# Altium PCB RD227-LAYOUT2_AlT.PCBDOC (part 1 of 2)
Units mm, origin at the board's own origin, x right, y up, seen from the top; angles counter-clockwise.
Board outline 90 x 40 mm, 4 copper layers (TOP, Mid-Layer 1, Mid-Layer 2, BOTTOM), stack 0.711 mm thick; 157 components, 70 nets, 396 pads, 438 vias.
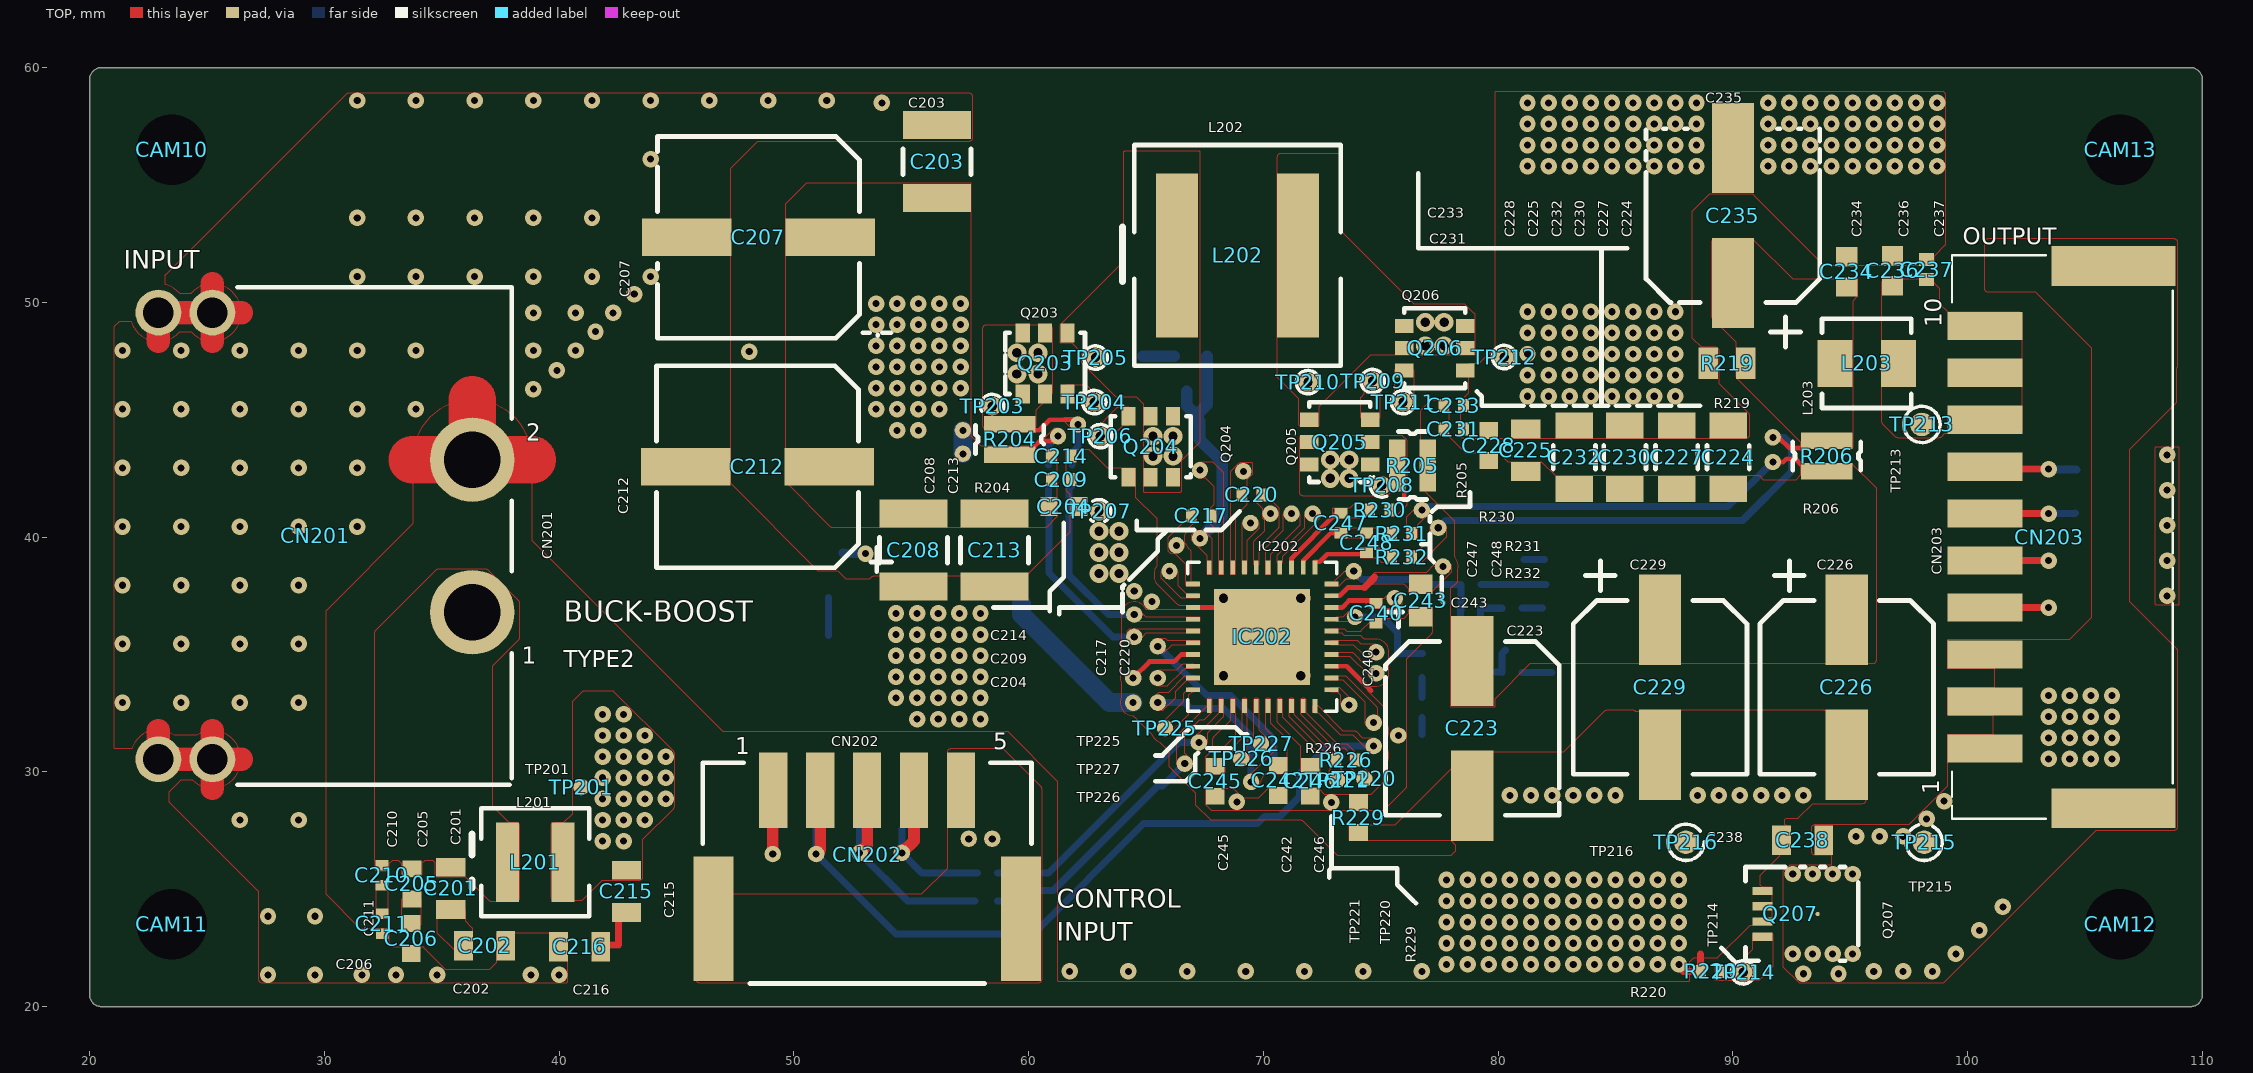
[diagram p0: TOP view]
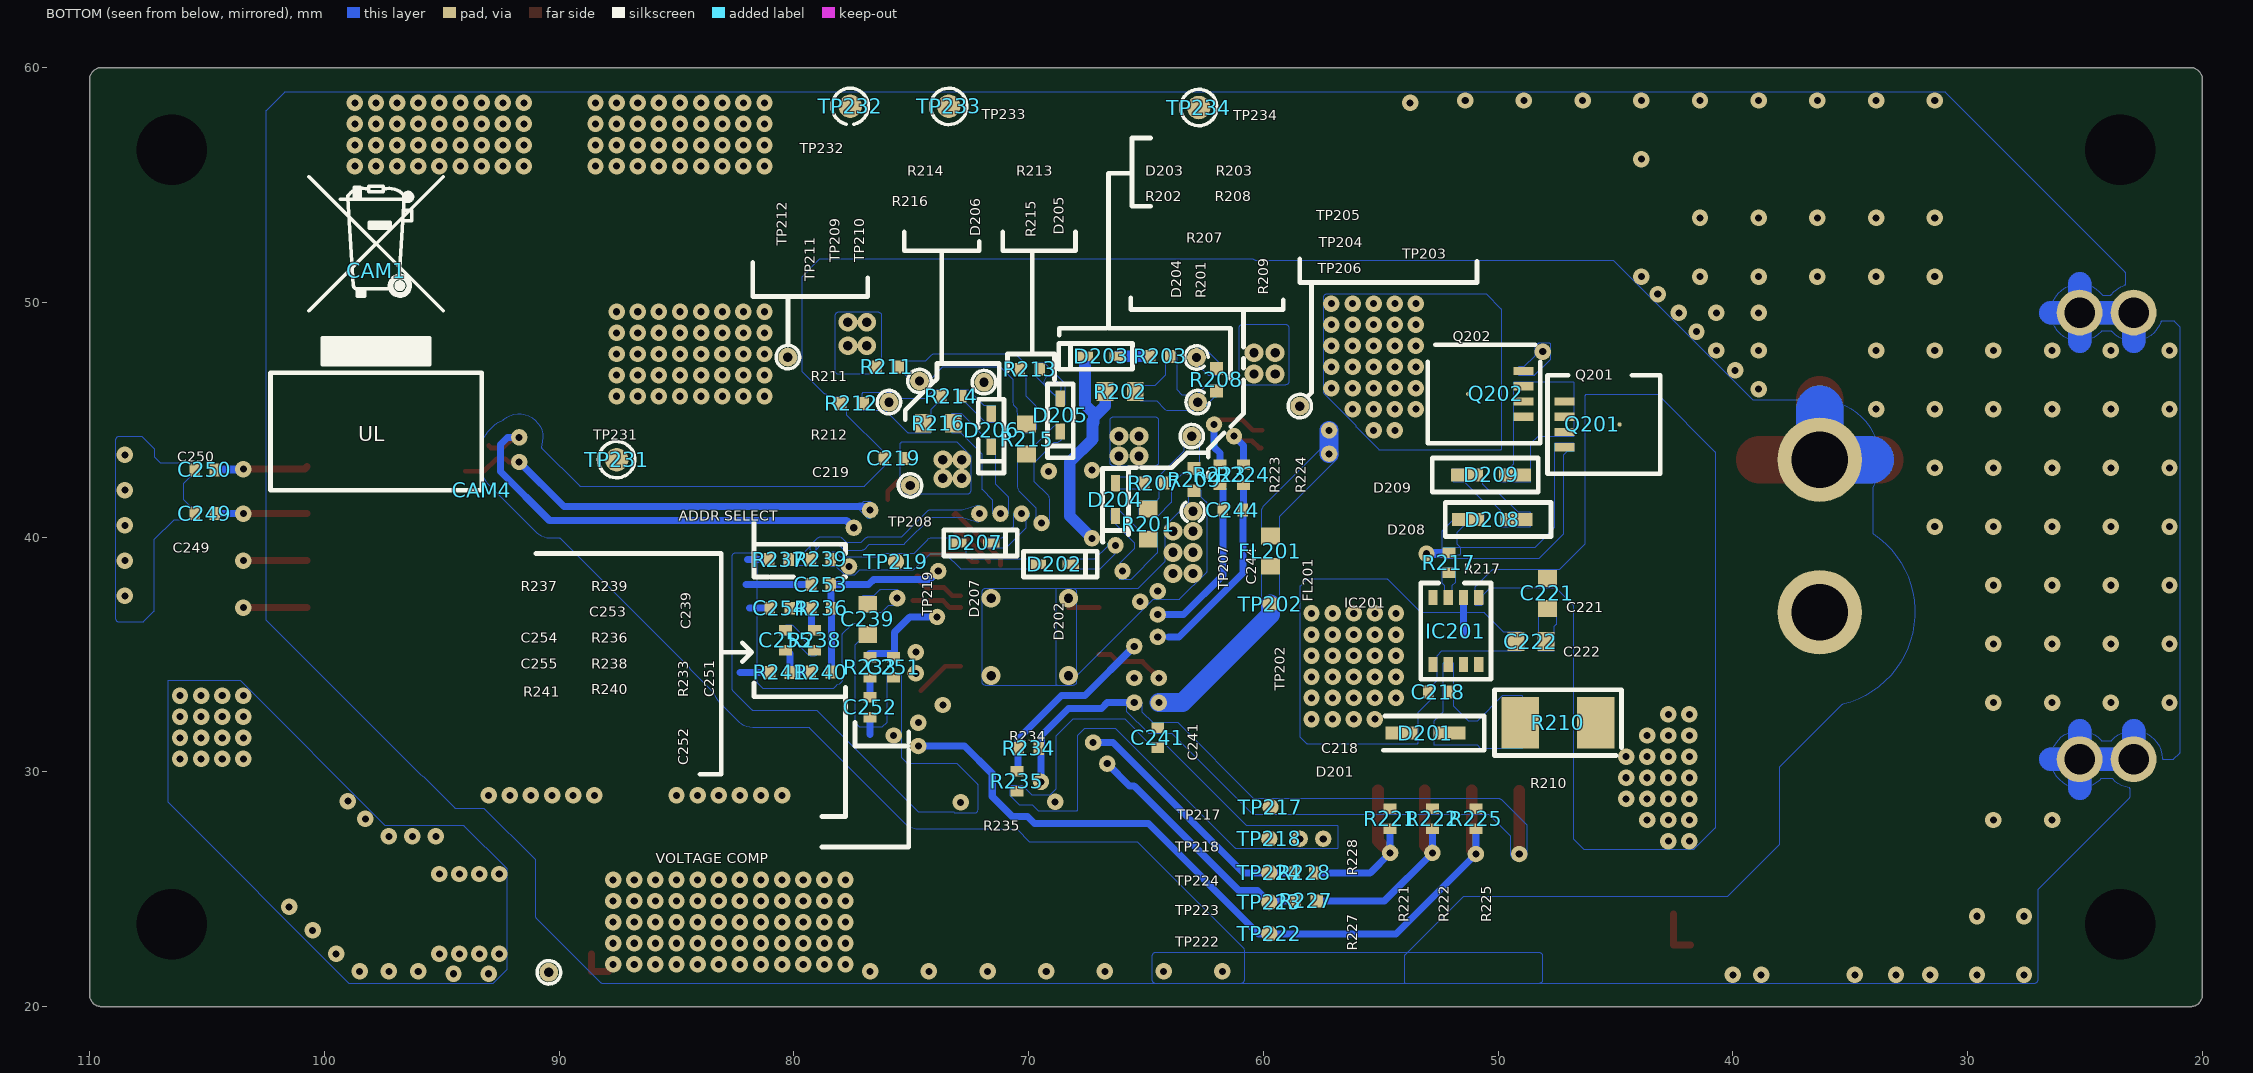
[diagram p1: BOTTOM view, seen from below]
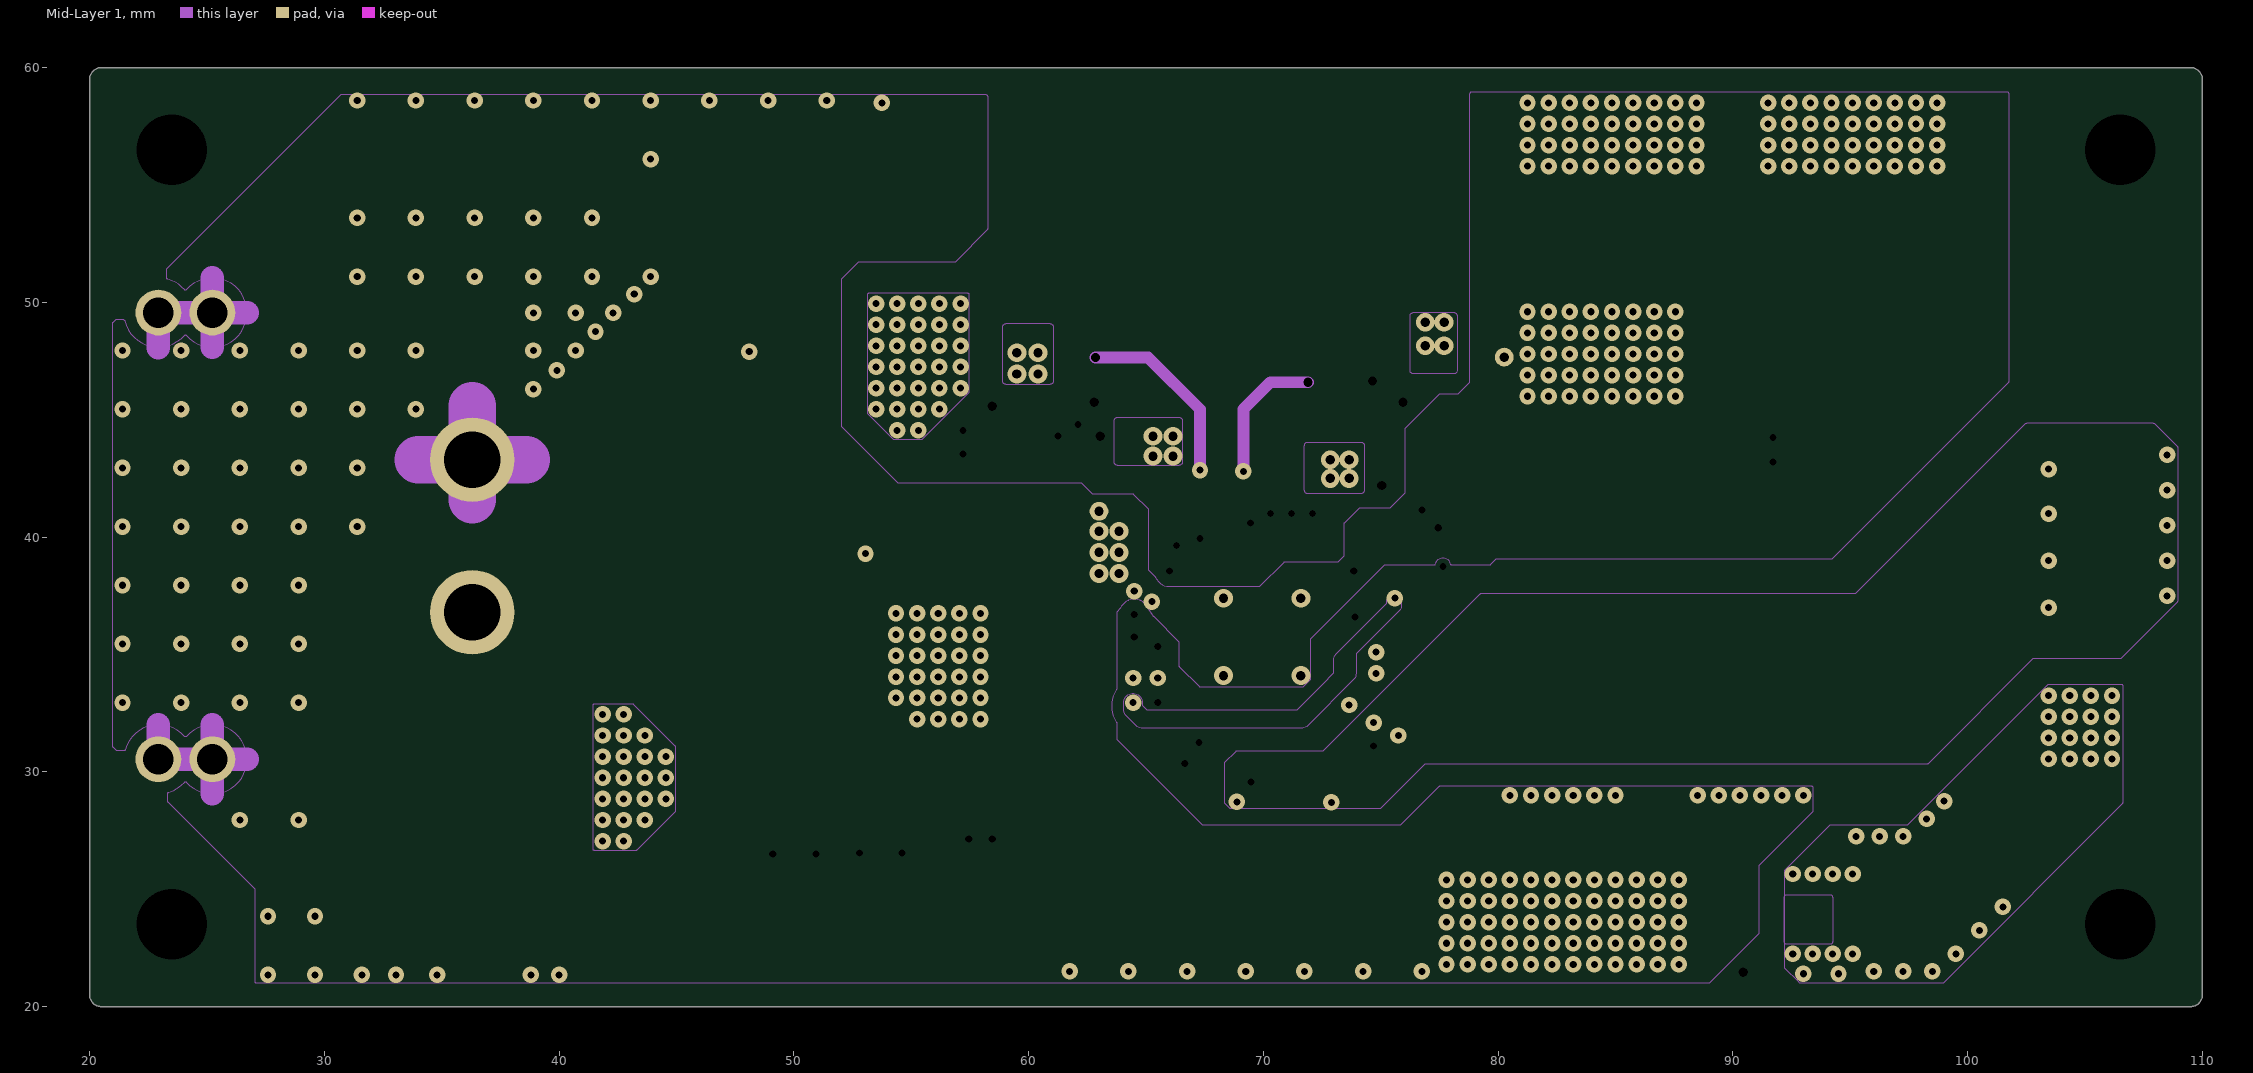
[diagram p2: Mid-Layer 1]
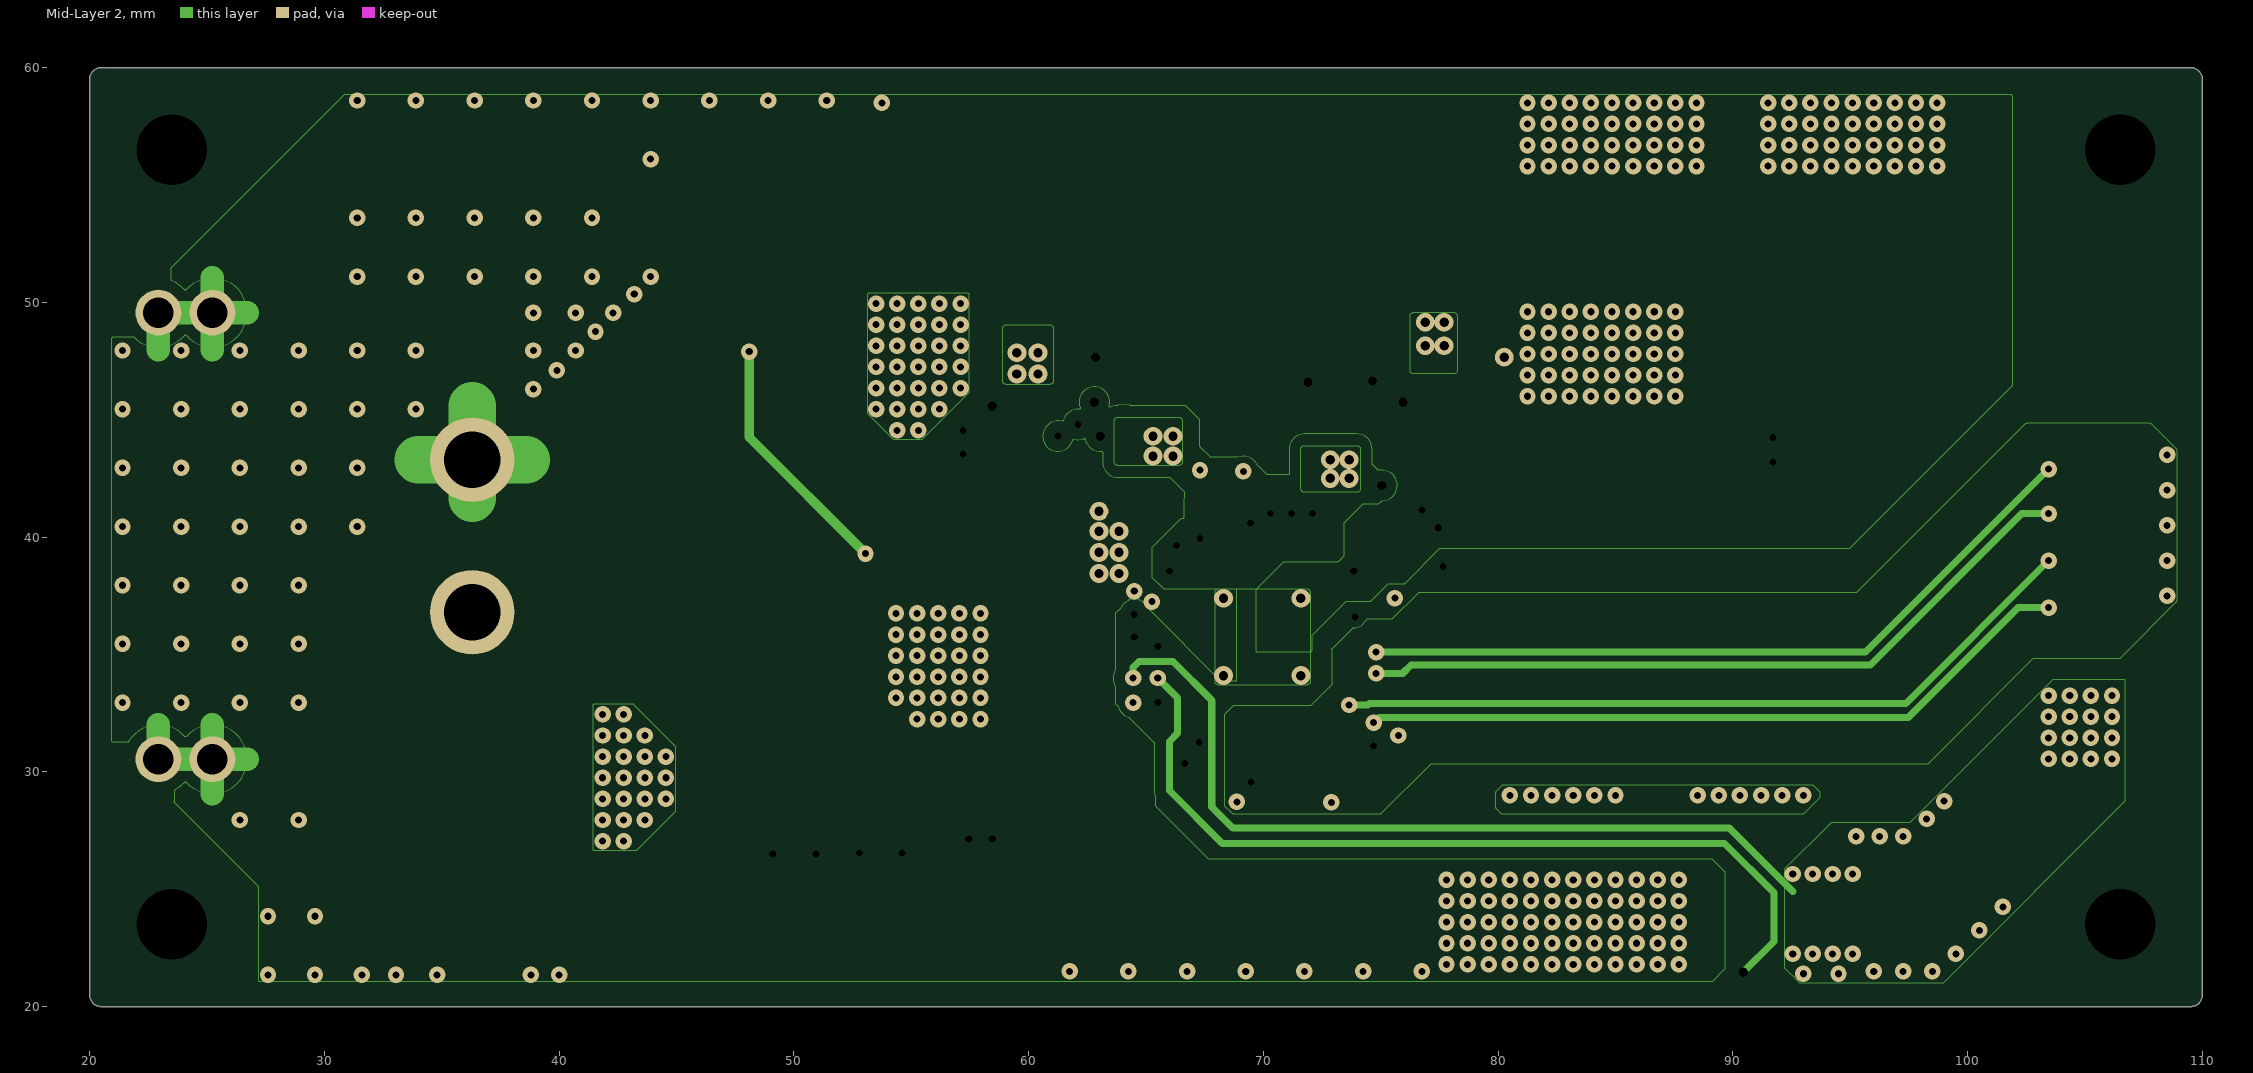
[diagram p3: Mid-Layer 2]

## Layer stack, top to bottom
Top Solder: solder mask 0.0102, Solder Resist, Dk 3.5
TOP: signal copper (thickness not stored)
Mid-Layer 1: signal copper 0.0356
Dielectric2: dielectric 0.32, FR-4, Dk 4.8
Mid-Layer 2: signal copper 0.0356
Dielectric3: dielectric 0.32, FR-4, Dk 4.8
BOTTOM: signal copper (thickness not stored)
Bottom Solder: solder mask 0.0102, Solder Resist, Dk 3.5

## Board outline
20,59.5 cw(c20.5,59.5) 20.5,60 109.5,60 cw(c109.5,59.5) 110,59.5 110,20.5 cw(c109.5,20.5) 109.5,20 20.5,20 cw(c20.5,20.5) 20,20.5

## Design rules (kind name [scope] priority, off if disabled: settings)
AssemblyTestPointUsage [All] p0: scope1count=1 scope1_0_kind=Board scope1_0_value=Board scope2count=1 scope2_0_kind=Board scope2_0_value=Board commentlength=0
AssemblyTestpoint [All] p0: scope1count=1 scope1_0_kind=Board scope1_0_value=Board scope2count=1 scope2_0_kind=Board scope2_0_value=Board commentlength=0
Clearance [All] p0: scope1count=1 scope1_0_kind=Board scope1_0_value=Board scope2count=1 scope2_0_kind=Board scope2_0_value=Board commentlength=0 gap=0.1
Clearance [All] p1: gap=0.1 ignorepadtopadclearanceinfootprint=TRUE except(0.11: SMDPad-Via; 0.15: SMDPad-SMDPad THPad-THPad Via-Via Via-Fill Via-Poly Via-Region; 0.25: SMDPad-Fill SMDPad-Poly SMDPad-Region THPad-Fill THPad-Poly THPad-Region Fill-Fill Fill-Poly Fill-Region Poly-Poly Poly-Region Region-Region; 1: Arc-Hole Track-Hole SMDPad-Hole THPad-Hole Fill-Hole Poly-Hole Region-Hole Text-Hole; 1.75: THPad-Via Via-Hole; 3: SMDPad-THPad)
ComponentClearance [All] p0: scope1count=1 scope1_0_kind=Board scope1_0_value=Board scope2count=1 scope2_0_kind=Board scope2_0_value=Board commentlength=0 gap=0.254 collisioncheckmode=3
DiffPairsRouting [All] p0: scope1count=1 scope1_0_kind=Board scope1_0_value=Board scope2count=1 scope2_0_kind=Board scope2_0_value=Board commentlength=0
FabricationTestPointUsage [All] p0: scope1count=1 scope1_0_kind=Board scope1_0_value=Board scope2count=1 scope2_0_kind=Board scope2_0_value=Board commentlength=0 valid=0 allowmultiple=FALSE
FabricationTestpoint [All] p0: scope1count=1 scope1_0_kind=Board scope1_0_value=Board scope2count=1 scope2_0_kind=Board scope2_0_value=Board commentlength=0 side=3 testpointundercomponent=TRUE minsize=1.016 maxsize=2.54 preferedsize=1.524 minholesize=0 maxholesize=1.016 preferedholesize=0.813 testpointgrid=0.025
FanoutControl Fanout_Default [All] p0: scope1count=1 scope1_0_kind=Board scope1_0_value=Board scope2count=1 scope2_0_kind=Board scope2_0_value=Board commentlength=30 // Fanout_Default (Default Rule)
FanoutControl Fanout_Small [All] p0 off: scope1count=1 scope1_0_kind=Board scope1_0_value=Board scope2count=1 scope2_0_kind=Board scope2_0_value=Board commentlength=84 // Protel DXP Scope 1 Expression Was: (CompPinCount < 5)   Fanout_Small (Default Rule)
FanoutControl Fanout_SOIC [All] p0 off: scope1count=1 scope1_0_kind=Board scope1_0_value=Board scope2count=1 scope2_0_kind=Board scope2_0_value=Board commentlength=71 // Protel DXP Scope 1 Expression Was: IsSOIC   Fanout_SOIC (Default Rule)
FanoutControl Fanout_LCC [All] p0 off: scope1count=1 scope1_0_kind=Board scope1_0_value=Board scope2count=1 scope2_0_kind=Board scope2_0_value=Board commentlength=69 // Protel DXP Scope 1 Expression Was: IsLCC   Fanout_LCC (Default Rule)
FanoutControl Fanout_BGA [All] p0 off: scope1count=1 scope1_0_kind=Board scope1_0_value=Board scope2count=1 scope2_0_kind=Board scope2_0_value=Board commentlength=69 // Protel DXP Scope 1 Expression Was: IsBGA   Fanout_BGA (Default Rule)
Height [All] p0: scope1count=1 scope1_0_kind=Board scope1_0_value=Board scope2count=1 scope2_0_kind=Board scope2_0_value=Board commentlength=0
HoleSize [All] p0: scope1count=1 scope1_0_kind=Board scope1_0_value=Board scope2count=1 scope2_0_kind=Board scope2_0_value=Board commentlength=0 absolutevalues=TRUE maxlimit=100 minlimit=0.001 maxpercent=80.000 minpercent=20.000
HoleSize [All] p1: absolutevalues=TRUE maxlimit=100 minlimit=0.001 maxpercent=80.000 minpercent=20.000
HoleToHoleClearance [All] p0: scope1count=1 scope1_0_kind=Board scope1_0_value=Board scope2count=1 scope2_0_kind=Board scope2_0_value=Board commentlength=0
HoleToHoleClearance [All] p1: gap=0.45 allowstackedmicrovias=FALSE
LayerPairs [All] p0: scope1count=1 scope1_0_kind=Board scope1_0_value=Board scope2count=1 scope2_0_kind=Board scope2_0_value=Board commentlength=0 enforce=TRUE
MinimumSolderMaskSliver [All] p0: scope1count=1 scope1_0_kind=Board scope1_0_value=Board scope2count=1 scope2_0_kind=Board scope2_0_value=Board commentlength=0
MinimumSolderMaskSliver [All] p1: minsoldermaskwidth=0.1
NetAntennae [All] p0: scope1count=1 scope1_0_kind=Board scope1_0_value=Board scope2count=1 scope2_0_kind=Board scope2_0_value=Board commentlength=0
NetAntennae [All] p1: netantennaetolerance=100
PasteMaskExpansion [All] p0: scope1count=1 scope1_0_kind=Board scope1_0_value=Board scope2count=1 scope2_0_kind=Board scope2_0_value=Board commentlength=0 expansion=0
PlaneClearance [All] p0: scope1count=1 scope1_0_kind=Board scope1_0_value=Board scope2count=1 scope2_0_kind=Board scope2_0_value=Board commentlength=0 clearance=0.001
PlaneClearance [All] p1: clearance=0.001
PlaneConnect [All] p0: scope1count=1 scope1_0_kind=Board scope1_0_value=Board scope2count=1 scope2_0_kind=Board scope2_0_value=Board commentlength=0 planeconnectstyle=Direct reliefexpansion=0.508 reliefentries=4 reliefconductorwidth=0.254 reliefairgap=0.254
PlaneConnect [All] p1: planeconnectstyle=Direct reliefexpansion=0.508 reliefentries=4 reliefconductorwidth=0.254 reliefairgap=0.254
PolygonConnect [All] p0: scope1count=1 scope1_0_kind=Board scope1_0_value=Board scope2count=1 scope2_0_kind=Board scope2_0_value=Board commentlength=0 connectstyle=Direct reliefconductorwidth=0.254 reliefentries=4 polygonreliefangle="90 Angle"
PolygonConnect [All] p1: connectstyle=Direct reliefconductorwidth=0.254 reliefentries=4 polygonreliefangle="90 Angle" airgapwidth=0.254
RoutingCorners [All] p0: scope1count=1 scope1_0_kind=Board scope1_0_value=Board scope2count=1 scope2_0_kind=Board scope2_0_value=Board commentlength=0 cornerstyle=45-Degree minsetback=2.54 maxsetback=2.54
RoutingLayers [All] p0: scope1count=1 scope1_0_kind=Board scope1_0_value=Board scope2count=1 scope2_0_kind=Board scope2_0_value=Board commentlength=0 top layer=Automatic mid layer 1=Automatic mid layer 2=Automatic bottom layer=Automatic
RoutingPriority [All] p0: scope1count=1 scope1_0_kind=Board scope1_0_value=Board scope2count=1 scope2_0_kind=Board scope2_0_value=Board commentlength=0
RoutingTopology [All] p0: scope1count=1 scope1_0_kind=Board scope1_0_value=Board scope2count=1 scope2_0_kind=Board scope2_0_value=Board commentlength=0 topology=Shortest
RoutingVias [All] p0: scope1count=1 scope1_0_kind=Board scope1_0_value=Board scope2count=1 scope2_0_kind=Board scope2_0_value=Board commentlength=0 holewidth=0.1 width=0.1 viastyle="Through Hole" minholewidth=0.001 minwidth=0.001 maxholewidth=100 maxwidth=100
RoutingVias [All] p1: holewidth=0.1 width=0.1 viastyle="Through Hole" minholewidth=0.001 minwidth=0.001 maxholewidth=100 maxwidth=100
ShortCircuit [All] p0: scope1count=1 scope1_0_kind=Board scope1_0_value=Board scope2count=1 scope2_0_kind=Board scope2_0_value=Board commentlength=0 allowed=FALSE
SilkToBoardRegionClearance [All] p0: scope1count=1 scope1_0_kind=Board scope1_0_value=Board scope2count=1 scope2_0_kind=Board scope2_0_value=Board commentlength=0
SilkToSilkClearance [All] p0: scope1count=1 scope1_0_kind=Board scope1_0_value=Board scope2count=1 scope2_0_kind=Board scope2_0_value=Board commentlength=0
SilkToSilkClearance [All] p1: silktosilkclearance=0.001
SilkToSolderMaskClearance [All] p0 off: scope1count=1 scope1_0_kind=Board scope1_0_value=Board scope2count=1 scope2_0_kind=Board scope2_0_value=Board commentlength=44 // Protel DXP Scope 1 Expression Was: IsPad
SilkToSolderMaskClearance [IsPad] p1: minsilkscreentomaskgap=0.11 clearancetoexposedcopper=TRUE
SolderMaskExpansion [All] p0: scope1count=1 scope1_0_kind=Board scope1_0_value=Board scope2count=1 scope2_0_kind=Board scope2_0_value=Board commentlength=0 expansion=0.001
SolderMaskExpansion [All] p1: expansion=0.001
UnRoutedNet [All] p0: scope1count=1 scope1_0_kind=Board scope1_0_value=Board scope2count=1 scope2_0_kind=Board scope2_0_value=Board commentlength=0
UnpouredPolygon [All] p0: scope1count=1 scope1_0_kind=Board scope1_0_value=Board scope2count=1 scope2_0_kind=Board scope2_0_value=Board commentlength=0
Width [All] p0: scope1count=1 scope1_0_kind=Board scope1_0_value=Board scope2count=1 scope2_0_kind=Board scope2_0_value=Board commentlength=0 maxlimit=1000 minlimit=2539.975 preferedwidth=0
Width [All] p1: maxlimit=1000 minlimit=2539.975 preferedwidth=0 toplayer_minwidth=0 midlayer1_minwidth=0 midlayer2_minwidth=0 bottomlayer_minwidth=0 minimp=50.000000 maximp=50.000000 favimp=50.000000
22 further rules are at their usual default settings.

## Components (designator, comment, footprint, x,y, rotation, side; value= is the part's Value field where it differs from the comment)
C201 "KC00060AKP" KC00060AKP 35.389,25.035 r90 top
C202 "KC00060AKP" KC00060AKP 36.828,22.597 r180 top
C203 "KCK03340AKP" KCK03340AKP 56.1,56 r270 top
C204 "KC00080AKP" KC00080AKP 61.5,41.3 r180 top
C205 "KC01340AKP" KC01340AKP 33.729,25.232 r90 top
C206 "KC01340AKP" KC01340AKP 33.7,22.9 r90 top
C207 "DC837K" DC837K 48.492,52.769 r0 top
C208 "KCK03340AKP" KCK03340AKP 55.1,39.45 r90 top
C209 "DC834K" DC834K 61.4,42.45 r180 top
C210 "DC834K" DC834K 32.45,25.6 r90 top
C211 "DC834K" DC834K 32.466,23.529 r90 top
C212 "DC837K" DC837K 48.45,43 r0 top
C213 "KCK03340AKP" KCK03340AKP 58.55,39.45 r90 top
C214 "DC834K" DC834K 61.4,43.45 r180 top
C215 "KC00060AKP" KC00060AKP 42.869,24.911 r90 top
C216 "KC00060AKP" KC00060AKP 40.874,22.545 r0 top
C217 "DC834K" DC834K 67.35,40.9 r0 top
C218 "DC934K" DC934K 52.55,33.4 r180 bottom
C219 "KC01540BKP01" KC01540BKP01 75.75,43.35 r0 bottom
C220 "DC834K" DC834K 69.5,41.8 r180 top
C221 "KC00080BKP" KC00080BKP 47.9,37.6 r90 bottom
C222 "KC00080BKP" KC00080BKP 48.6,35.55 r180 bottom
C223 "DC843R" DC843R 78.9,31.85 r90 top
C224 "KC00140AKP" KC00140AKP 89.8,43.4 r270 top
C225 "KC00060AKP" KC00060AKP 81.175,43.7 r270 top
C226 "DC843R" DC843R 94.85,33.6 r90 top
C227 "KC00140AKP" KC00140AKP 87.6,43.4 r270 top
C228 "KC00080AKP" KC00080AKP 79.6,43.9 r270 top
C229 "DC843R" DC843R 86.9,33.6 r90 top
C230 "KC00140AKP" KC00140AKP 85.4,43.4 r270 top
C231 "DC834K" DC834K 78.1,44.6 r180 top
C232 "KC00140AKP" KC00140AKP 83.25,43.4 r270 top
C233 "DC834K" DC834K 78.1,45.6 r180 top
C234 "KCK02380AKP01" KCK02380AKP01 94.85,51.3 r270 top
C235 "DC843R" DC843R 90,53.7 r270 top
C236 "KCK02380AKP01" KCK02380AKP01 96.8,51.35 r270 top
C237 "KC01540AKP" KC01540AKP 98.25,51.4 r270 top
C238 "KC00060AKP" KC00060AKP 92.966,27.09 r0 top
C239 "KC00080BKP" KC00080BKP 76.85,36.5 r90 bottom
C240 "DC834K" DC834K 74.8,36.75 r90 top
C241 "DC934K" DC934K 64.5,31.45 r90 bottom
C242 "KC01670AKP" KC01670AKP 70.631,29.633 r270 top
C243 "KC01560AKP" KC01560AKP 76.7,37.3 r270 top
C244 "DC934K" DC934K 61.3,41.15 r0 bottom
C245 "KC00080AKP" KC00080AKP 67.95,29.6 r270 top
C246 "KC00080AKP" KC00080AKP 72,29.6 r270 top
C247 "DC834K" DC834K 73.3,40.6 r90 top
C248 "DC834K" DC834K 74.4,39.75 r90 top
C249 "DC934K" DC934K 105.1,41 r180 bottom
C250 "DC934K" DC934K 105.092,42.864 r180 bottom
C251 "DC934K" DC934K 75.75,34.45 r90 bottom
C252 "DC934K" DC934K 76.75,32.75 r90 bottom
C253 "DC934K" DC934K 78.845,37.981 r180 bottom
C254 "DC934K" DC934K 80.599,36.972 r180 bottom
C255 "DC934K" DC934K 80.35,35.6 r90 bottom
CAM1 "CAM_LOGO_MARK_WEEE-B" CAM_LOGO_MARK_WEEE-B 97.8,51.35 r0 bottom
CAM4 "Local_ULCMN-B" Local_ULCMN-B 93.3,42 r0 bottom
CAM10 "NTC300" NTC300 23.5,56.5 r0 top
CAM11 "NTC300" NTC300 23.5,23.5 r0 top
CAM12 "NTC300" NTC300 106.5,23.5 r0 top
CAM13 "NTC300" NTC300 106.5,56.5 r0 top
CN201 "Local_HVH-280-2P-6_5DS" Local_HVH-280-2P-6_5DS 36.3,36.8 r270 top
CN202 "Local_502352-0501" Local_502352-0501 53.121,25.687 r0 top
CN203 "Local_502352-1000" Local_502352-1000 104,40 r90 top
D201 "D9K022" D9K022 53.1,31.65 r0 bottom
D202 "D8101D1BKP" D8101D1BKP 68.9,38.85 r0 bottom
D203 "D8101D1BKP" D8101D1BKP 66.9,47.7 r180 bottom
D204 "D8101D1BKP" D8101D1BKP 66.3,41.6 r90 bottom
D205 "D8101D1BKP" D8101D1BKP 68.65,45.2 r90 bottom
D206 "D8101D1BKP" D8101D1BKP 71.6,44.55 r90 bottom
D207 "D8101D1BKP" D8101D1BKP 72.3,39.75 r0 bottom
D208 "D9K022" D9K022 50.25,40.75 r0 bottom
D209 "D9K022" D9K022 50.3,42.65 r180 bottom
FL201 "KC00080BKP" KC00080BKP 59.7,39.4 r270 bottom
IC201 "SN00281BKP" SN00281BKP 51.8,36 r180 bottom
IC202 "Local_MAX25432BATLGV+-A" Local_MAX25432BATLGV+-A 69.95,35.75 r0 top
L201 "Local_XEL-4030-471MEC" Local_XEL-4030-471MEC 38.984,26.149 r0 top
L202 "Local_XAL8080-103MED" Local_XAL8080-103MED 68.9,52 r0 top
L203 "Local_IHLP1212BZEVR22M5A" Local_IHLP1212BZEVR22M5A 95.7,47.4 r0 top
Q201 "SN00612BKP" SN00612BKP 45.5,44.8 r90 bottom
Q202 "SN00612BKP" SN00612BKP 50.6,46.1 r270 bottom
Q203 "Local_TSOP6F" Local_TSOP6F 60.7,47.4 r0 top
Q204 "Local_TSOP6F" Local_TSOP6F 65.2,43.85 r180 top
Q205 "Local_TSOP6F" Local_TSOP6F 73.25,44.05 r90 top
Q206 "Local_TSOP6F" Local_TSOP6F 77.3,48.05 r270 top
Q207 "SN00612AKP" SN00612AKP 92.935,23.948 r270 top
R201 "KC00080BKP" KC00080BKP 64.9,40.55 r270 bottom
R202 "KC00080BKP" KC00080BKP 66.1,46.2 r0 bottom
R203 "DC934K" DC934K 64.4,47.7 r0 bottom
R204 "Local_KRL2012" Local_KRL2012 59.19,44.166 r90 top
R205 "Local_KRL2012" Local_KRL2012 76.35,43.05 r0 top
R206 "Local_KRL2012" Local_KRL2012 94,43.45 r90 top
R207 "DC934K" DC934K 64.65,42.3 r0 bottom
R208 "KC01310BKP" KC01310BKP 62,46.7 r270 bottom
R209 "KC01310BKP" KC01310BKP 62.95,42.45 r90 bottom
R210 "DR901RF" DR901RF 47.45,32.1 r180 bottom
R211 "KC01310BKP" KC01310BKP 76.05,47.25 r180 bottom
R212 "KC01310BKP" KC01310BKP 77.55,45.7 r180 bottom
R213 "DC934K" DC934K 69.95,47.15 r180 bottom
R214 "DC934K" DC934K 73.3,46 r180 bottom
R215 "KC00080BKP" KC00080BKP 70.09,44.175 r270 bottom
R216 "KC00080BKP" KC00080BKP 73.85,44.85 r180 bottom
R217 "DR924K" DR924K 52.1,38.9 r90 bottom
R219 "DR810K" DR810K 89.75,47.4 r0 top
R220 "DR824K" DR824K 89.051,21.503 r0 top
R221 "DR924K" DR924K 54.6,28 r270 bottom
R222 "DR924K" DR924K 52.8,28 r270 bottom
R223 "DC934K" DC934K 61.85,42.65 r90 bottom
R224 "DC934K" DC934K 60.85,42.65 r90 bottom
R225 "DR924K" DR924K 50.95,28 r270 bottom
R226 "DR824K" DR824K 73.5,30.5 r180 top
R227 "KC01310BKP" KC01310BKP 58.2,24.5 r180 bottom
R228 "DR924K" DR924K 58.25,25.7 r180 bottom
R229 "KC00080AKP" KC00080AKP 74.05,28.05 r90 top
R230 "DR824K" DR824K 74.95,41.15 r180 top
R231 "DR824K" DR824K 75.9,40.15 r180 top
R232 "DR824K" DR824K 75.9,39.15 r180 top
R233 "DR924K" DR924K 76.75,34.45 r90 bottom
R234 "DR924K" DR924K 70,31 r0 bottom
R235 "DR924K" DR924K 70.5,29.6 r270 bottom
R236 "KC00050BKP" KC00050BKP 78.829,36.97 r180 bottom
R237 "DR924K" DR924K 80.635,39.039 r0 bottom
R238 "DR924K" DR924K 79.113,35.602 r90 bottom
R239 "DR924K" DR924K 78.85,39.05 r0 bottom
R240 "DR924K" DR924K 78.85,34.251 r180 bottom
R241 "DR924K" DR924K 80.592,34.24 r180 bottom
TP201 "TL0.7_A_noMM" TL0.7_A_noMM 40.95,29.35 r0 top
TP202 "TL0.7_B_noMM" TL0.7_B_noMM 59.7,37.15 r0 bottom
TP203 "Local_TL0.4_TH-A" Local_TL0.4_TH-A#1 58.45,45.583 r0 top
TP204 "Local_TL0.4_TH-A" Local_TL0.4_TH-A#1 62.8,45.75 r0 top
TP205 "Local_TL0.4_TH-A" Local_TL0.4_TH-A#1 62.85,47.65 r0 top
TP206 "Local_TL0.4_TH-A" Local_TL0.4_TH-A#1 63.05,44.3 r0 top
TP207 "Local_TL0.4_TH-A" Local_TL0.4_TH-A#2 63,41.1 r0 top
TP208 "Local_TL0.4_TH-A" Local_TL0.4_TH-A#1 75.05,42.2 r0 top
TP209 "Local_TL0.4_TH-A" Local_TL0.4_TH-A#1 74.65,46.65 r0 top
TP210 "Local_TL0.4_TH-A" Local_TL0.4_TH-A#1 71.9,46.6 r0 top
TP211 "Local_TL0.4_TH-A" Local_TL0.4_TH-A#1 75.95,45.75 r0 top
TP212 "Local_TL0.4_TH-A" Local_TL0.4_TH-A#2 80.258,47.67 r0 top
TP213 "Local_TP-100-A" Local_TP-100-A 98.05,44.8 r0 top
TP214 "Local_TL0.4_TH-A" Local_TL0.4_TH-A#1 90.437,21.463 r0 top
TP215 "Local_TP-100-A" Local_TP-100-A 98.15,27 r0 top
TP216 "Local_TP-100-A" Local_TP-100-A 88,27 r0 top
TP217 "TL0.7_B_noMM" TL0.7_B_noMM 59.7,28.5 r0 bottom
TP218 "TL0.7_B_noMM" TL0.7_B_noMM 59.75,27.15 r0 bottom
TP219 "TL0.7_B_noMM" TL0.7_B_noMM 75.65,38.95 r0 bottom
TP220 "TL0.7_A_noMM" TL0.7_A_noMM 74.3,29.7 r0 top
TP221 "TL0.7_A_noMM" TL0.7_A_noMM 73.15,29.65 r0 top
TP222 "TL0.7_B_noMM" TL0.7_B_noMM 59.75,23.1 r0 bottom
TP223 "TL0.7_B_noMM" TL0.7_B_noMM 59.75,24.45 r0 bottom
TP224 "TL0.7_B_noMM" TL0.7_B_noMM 59.75,25.7 r0 bottom
TP225 "TL0.7_A_noMM" TL0.7_A_noMM 65.808,31.864 r0 top
TP226 "TL0.7_A_noMM" TL0.7_A_noMM 69.05,30.55 r0 top
TP227 "TL0.7_A_noMM" TL0.7_A_noMM 69.9,31.2 r0 top
TP231 "Local_TP-100-B" Local_TP-100-B 87.55,43.3 r0 bottom
TP232 "Local_TP-100-B" Local_TP-100-B 77.6,58.35 r0 bottom
TP233 "Local_TP-100-B" Local_TP-100-B 73.4,58.35 r0 bottom
TP234 "Local_TP-100-B" Local_TP-100-B 62.75,58.3 r0 bottom

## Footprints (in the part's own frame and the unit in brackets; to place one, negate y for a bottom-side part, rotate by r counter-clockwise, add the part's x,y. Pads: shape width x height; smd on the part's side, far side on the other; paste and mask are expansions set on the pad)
CAM_LOGO_MARK_WEEE-B [mm] "KC00080BKP"
  silkscreen extent -2.86,-4 2.86,4
D9K022 [mm] "KC00080BKP"
  rect 1.36x0.55 smd paste-1.36 mask+0: A(1.025,0) C(-1.025,0)
  silkscreen extent -2.51,-0.72 1.79,0.72
D8101D1BKP [mm] "KC00080BKP"
  rect 0.7x0.4 smd paste-0.7 mask+0: A(0.7,0) C(-0.7,0)
  silkscreen extent -1.82,-0.55 1.32,0.55
DC834K [mm] "KC00080BKP"
  rect 0.45x0.55 smd paste-0.55 mask+0: 1(-0.425,0) 2(0.425,0)
DC837K [mm] "KC00080BKP"
  rect 3.82x1.6 smd paste-3.82 mask+0: 1(-3.06,0) 2(3.06,0)
  silkscreen extent -4.3,-4.3 5.64,4.3
DC843R [mm] "KC00080BKP"
  rect 3.85x1.8 smd paste-3.85 mask+0: 1(-2.875,0) 2(2.875,0)
  silkscreen extent -3.7,-3.7 5.14,3.7
DC934K [mm] "KC00080BKP"
  rect 0.45x0.55 smd paste-0.55 mask+0: 1(-0.425,0) 2(0.425,0)
DR810K [mm] "KC00080BKP"
  rect 0.83x1.35 smd paste-1.35 mask+0: 1(-0.8,0) 2(0.8,0)
DR824K [mm] "KC00080BKP"
  rect 0.45x0.55 smd paste-0.55 mask+0: 1(-0.425,0) 2(0.425,0)
DR901RF [mm] "KC00080BKP"
  rect 1.6x2.2 smd paste-2.2 mask+0: 1(-1.6,0) 2(1.6,0)
  silkscreen extent -2.7,-1.4 2.7,1.4
DR924K [mm] "KC00080BKP"
  rect 0.45x0.55 smd paste-0.55 mask+0: 1(-0.425,0) 2(0.425,0)
KC00050BKP [mm] "KC00080BKP"
  rect 0.45x0.55 smd paste-0.55 mask+0: 1(-0.425,0) 2(0.425,0)
KC00060AKP [mm] "KC00080BKP"
  rect 0.8x1.25 smd paste-1.25 mask+0: 1(-0.9,0) 2(0.9,0)
KC00080AKP [mm] "KC00080BKP"
  rect 0.72x0.8 smd paste-0.8 mask+0: 1(-0.64,0) 2(0.64,0)
KC00080BKP [mm] "KC00080BKP"
  rect 0.72x0.8 smd paste-0.8 mask+0: 1(-0.64,0) 2(0.64,0)
KC00140AKP [mm] "KC00080BKP"
  rect 1.1x1.6 smd paste-1.6 mask+0: 1(-1.35,0) 2(1.35,0)
  silkscreen extent -0.5,-0.9 0.5,0.9
KC01310BKP [mm] "KC00080BKP"
  rect 0.55x0.55 smd paste-0.55 mask+0: 1(-0.475,0) 2(0.475,0)
KC01340AKP [mm] "KC00080BKP"
  rect 0.72x0.8 smd paste-0.8 mask+0: 1(-0.64,0) 2(0.64,0)
KC01540AKP [mm] "KC00080BKP"
  rect 0.55x0.65 smd paste-0.65 mask+0: 1(-0.425,0) 2(0.425,0)
KC01540BKP01 [mm] "KC00080BKP"
  rect 0.45x0.55 smd paste-0.55 mask+0: 1(-0.425,0) 2(0.425,0)
KC01560AKP [mm] "KC00080BKP"
  rect 0.83x1 smd paste-1 mask+0: 1(-0.695,0) 2(0.695,0)
KC01670AKP [mm] "KC00080BKP"
  rect 0.72x0.8 smd paste-0.8 mask+0: 1(-0.64,0) 2(0.64,0)
KCK02380AKP01 [mm] "KC00080BKP"
  rect 0.82x0.9 smd paste-0.9 mask+0: 1(-0.64,0) 2(0.64,0)
KCK03340AKP [mm] "KC00080BKP"
  rect 1.2x2.9 smd paste-2.9 mask+0: 1(-1.55,0) 2(1.55,0)
  silkscreen extent -0.55,-1.45 0.55,1.45
Local_502352-0501 [mm] "KC00080BKP"
  rect 1.2x3.2 smd paste-3.2 mask+0: 1(-4,3.53) 2(-2,3.53) 3(0,3.53) 4(2,3.53) 5(4,3.53)
  rect 1.7x5.3 smd paste-5.3 mask+0: 1T(-6.55,-1.95) 2T(6.55,-1.95)
  silkscreen extent -7,-4.7 7,4.7
Local_502352-1000 [mm] "KC00080BKP"
  rect 1.2x3.2 smd paste-3.2 mask+0: 1(-9,3.265) 2(-7,3.265) 3(-5,3.265) 4(-3,3.265) 5(-1,3.265) 6(1,3.265) 7(3,3.265) 8(5,3.265) 9(7,3.265) 10(9,3.265)
  rect 1.7x5.3 smd paste-5.3 mask+0: 1T(-11.55,-2.215) 2T(11.55,-2.215)
  silkscreen extent -12,-4.73 12,4.66
Local_HVH-280-2P-6_5DS [mm] "KC00080BKP"
  round 3.6 hole 2.4 paste-3.6 mask+0: 1(0,0) 2(-6.5,0)
  round 1.95 hole 1.3 paste-1.95 mask+0: 1T(6.265,-13.37) 2T(6.265,-11.07) 3T(-12.765,-11.07) 4T(-12.765,-13.37)
  silkscreen extent -13.85,-10 7.35,1.68
Local_IHLP1212BZEVR22M5A [mm] "KC00080BKP"
  rect 1.5x2 smd paste-2 mask+0: 1(-1.35,0) 2(1.35,0)
  silkscreen extent -1.9,-1.9 1.9,1.9
Local_KRL2012 [mm] "KC00080BKP"
  rect 0.7x2.2 smd paste-2.2 mask+0: 1(-0.65,0) 2(0.65,0)
  silkscreen extent -0.6,-1.45 0.6,1.45
Local_MAX25432BATLGV+-A [mm] "KC00080BKP"
  rect 0.6x0.2 smd paste-0.6 mask+0: 1(-2.948,2.25) 2(-2.948,1.75) 3(-2.948,1.25) 4(-2.948,0.75) 5(-2.948,0.25) 6(-2.948,-0.25) 7(-2.948,-0.75) 8(-2.948,-1.25) 9(-2.948,-1.75) 10(-2.948,-2.25) 21(2.948,-2.25) 22(2.948,-1.75) 23(2.948,-1.25) 24(2.948,-0.75) 25(2.948,-0.25) 26(2.948,0.25) 27(2.948,0.75) 28(2.948,1.25) 29(2.948,1.75) 30(2.948,2.25)
  rect 0.2x0.6 smd paste-0.6 mask+0: 11(-2.25,-2.948) 12(-1.75,-2.948) 13(-1.25,-2.948) 14(-0.75,-2.948) 15(-0.25,-2.948) 16(0.25,-2.948) 17(0.75,-2.948) 18(1.25,-2.948) 19(1.75,-2.948) 20(2.25,-2.948) 31(2.25,2.948) 32(1.75,2.948) 33(1.25,2.948) 34(0.75,2.948) 35(0.25,2.948) 36(-0.25,2.948) 37(-0.75,2.948) 38(-1.25,2.948) 39(-1.75,2.948) 40(-2.25,2.948)
  rect 4.089x4.089 smd paste-4.089 mask+0: 41(0,0)
  silkscreen extent -3.17,-3.17 3.17,3.17
Local_TL0.4_TH-A#1 [mm] "KC00080BKP"
  round 0.8 / inner round 0 / far side round 0.8 hole 0.4 paste-0.8 mask+0: 1(0,0)
  silkscreen extent -0.5,-0.21 0.5,0.5
Local_TL0.4_TH-A#2 [mm] "KC00080BKP"
  round 0.8 hole 0.4 paste-0.8 mask+0: 1(0,0)
  silkscreen extent -0.35,-0.43 0.5,0.5
Local_TP-100-A [mm] "KC00080BKP"
  round 1 smd paste-1 mask+0: 1(0,0)
  silkscreen extent -0.77,-0.77 0.77,0.77
Local_TP-100-B [mm] "KC00080BKP"
  round 1 smd paste-1 mask+0: 1(0,0)
  silkscreen extent -0.77,-0.77 0.77,0.77
Local_TSOP6F [mm] "KC00080BKP"
  rect 0.6x0.8 smd paste-0.8 mask+0: 1(-0.95,-1.3) 2(0,-1.3) 3(0.95,-1.3) 4(0.95,1.3) 5(0,1.3) 6(-0.95,1.3)
  silkscreen extent -1.7,-1.3 1.7,1.3
Local_ULCMN-B [mm] "KC00080BKP"
  silkscreen extent 0,-5 9,0
Local_XAL8080-103MED [mm] "KC00080BKP"
  rect 1.78x7 smd paste-7 mask+0: 1(-2.58,0) 2(2.58,0)
  silkscreen extent -4.9,-4.7 4.4,4.7
Local_XEL-4030-471MEC [mm] "KC00080BKP"
  rect 0.98x3.4 smd paste-3.4 mask+0: 1(-1.185,0) 2(1.185,0)
  silkscreen extent -2.7,-2.3 2.3,2.3
NTC300 [mm] "KC00080BKP"
  round 0 hole 3 unplated paste-3.5 mask+0: ""(0,0)
SN00281BKP [mm] "KC00080BKP"
  rect 0.4x0.65 smd paste-0.65 mask+0: 1(0.975,1.425) 2(0.325,1.425) 3(-0.325,1.425) 4(-0.975,1.425) 5(-0.975,-1.425) 6(-0.325,-1.425) 7(0.325,-1.425) 8(0.975,-1.425)
  silkscreen extent -1.5,-2.05 1.5,2.05
SN00612AKP [mm] "KC00080BKP"
  rect 0.35x0.85 smd paste-0.85 mask+0: 1(-0.975,-1.675) 2(-0.325,-1.675) 3(0.325,-1.675) 4(0.975,-1.675)
  round 0.178 smd paste-0.178 mask+0: 5(0,0.675)
  silkscreen extent -2,-2.4 2,2.4
SN00612BKP [mm] "KC00080BKP"
  rect 0.35x0.85 smd paste-0.85 mask+0: 1(0.975,1.675) 2(0.325,1.675) 3(-0.325,1.675) 4(-0.975,1.675)
  round 0.178 smd paste-0.178 mask+0: 5(0,-0.675)
  silkscreen extent -2.1,-2.4 2.1,2.4
TL0.7_A_noMM [mm] "KC00080BKP"
  round 0.7 smd paste-0.8 mask+0: 1(0,0)
TL0.7_B_noMM [mm] "KC00080BKP"
  round 0.7 smd paste-0.8 mask+0: 1(0,0)

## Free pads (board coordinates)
  round 0.7 / inner round 0 / far side round 0.7 hole 0.3 paste-0.7 mask+0: ""(49.1,26.5) ""(50.95,26.5) ""(52.8,26.55) ""(54.6,26.55) ""(57.2,43.55) ""(57.2,44.55) ""(57.45,27.15) ""(58.45,27.15) ""(61.25,44.3) ""(62.1,44.8) ""(64.5,35.75) ""(64.5,36.7) ""(65.5,32.95) ""(65.5,35.35) ""(66,38.55) ""(66.3,39.65) ""(66.65,30.35) ""(67.25,31.25) ""(67.3,39.95) ""(69.45,40.6) ""(69.475,29.575) ""(70.3,41) ""(71.2,41) ""(72.1,41) ""(73.85,38.55) ""(73.9,36.6) ""(74.7,31.1) ""(76.75,41.15) ""(77.45,40.4) ""(77.65,38.75) ""(91.7,43.2) ""(91.7,44.25)

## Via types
v1: diameter 0.7, hole 0.3, TOP to BOTTOM, 412 vias
v2: diameter 0.8, hole 0.4, TOP to BOTTOM, 26 vias

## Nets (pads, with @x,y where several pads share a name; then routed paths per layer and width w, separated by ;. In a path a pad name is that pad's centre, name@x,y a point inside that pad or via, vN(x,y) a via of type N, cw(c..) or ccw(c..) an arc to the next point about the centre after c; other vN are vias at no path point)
ADDR: IC202.34 pad.@72.1,41 R237.1 R239.2
ALERT: CN202.2 IC202.20 pad.@50.95,26.5 pad.@74.7,31.1 R225.2 TP222.1 | length 32.9
  TOP w0.5: pad.@50.95,26.5 51.121,26.671 CN202.2@51.121,29.217
  BOTTOM w0.3: R225.2@50.95,27.575 pad.@50.95,26.5 54.35,23.1 TP222.1@59.75,23.1 60.2,23.1 64.9,27.8 69.75,27.8 70.05,28.1 70.7,28.1 71.55,28.95 71.55,29.921 72.729,31.1 pad.@74.7,31.1
BIAS: C243.1 D202.A D207.A IC202.29 pad.@77.65,38.75 R239.1 TP219.1 | length 2.2
  TOP w0.2: IC202.29@72.898,37.5 73.25,37.5 73.6,37.85 74.3,37.85
  TOP w0.3: 74.3,37.85 74.743,38.293
BST1: C217.1 D202.C IC202.1 pad.@66.3,39.65
BST2: C220.1 D207.C IC202.36 pad.@70.3,41
CSN1: pad.@62.1,44.8 Q203.1 Q203.2 Q203.5 Q203.6 R204.2 R223.2 TP203.1 | length 4.1
  TOP w0.2: R204.2@60.05,44.55 60.45,44.55 60.9,45 61.9,45 pad.@62.1,44.8
  BOTTOM w0.3: R223.2@61.85,43.075 61.85,43.58 62.1,43.83 pad.@62.1,44.8
  other v2: 59.5,46.95 60.4,46.95 59.5,47.85 60.4,47.85
CSN2: C234.2 C235.2 L203.1 pad.@77.45,40.4 pad.@91.7,44.25 R206.2 R219.2 R232.1 | length 19.7
  TOP w0.2: pad.@91.7,44.25 92,44.25 92,44.2 92.4,43.8 92.9,43.8 R206.2@93,43.9
  BOTTOM w0.2: pad.@91.7,44.25 pad.@91.85,44.25
  BOTTOM w0.3: pad.@77.45,40.4 77.75,40.7 90.4,40.7 92.5,42.8 92.5,43.95 92.2,44.25 pad.@91.85,44.25
CSP1: C203.2 C204.2 C207.2 C208.2 C209.2 C212.2 C213.2 C214.2 FL201.1 pad.@57.2,43.55 pad.@57.2,44.55 pad.@61.25,44.3 Q202.5 R204.1 R224.2 | length 3.7
  TOP w0.2: R204.1@60.1,43.8 60.185,43.8 60.485,44.1 61.05,44.1 pad.@61.25,44.3
  BOTTOM w0.3: R224.2@60.85,43.075 60.85,43.9 pad.@61.25,44.3
  BOTTOM w0.8: pad.@57.2,43.55 pad.@57.2,44.55
  other v1: 54.4,44.55 55.3,44.55 53.5,45.45 54.4,45.45 55.3,45.45 56.2,45.45 53.5,46.35 54.4,46.35 55.3,46.35 56.2,46.35 57.1,46.35 53.5,47.25 54.4,47.25 55.3,47.25 56.2,47.25 57.1,47.25 53.5,48.15 54.4,48.15 55.3,48.15 56.2,48.15 57.1,48.15 53.5,49.05 54.4,49.05 55.3,49.05 56.2,49.05 57.1,49.05 53.5,49.95 54.4,49.95 55.3,49.95 56.2,49.95 57.1,49.95
CSP2: C219.1 Q205.1 Q205.2 Q205.5 Q205.6 R205.1 R230.1 TP208.1 | length 1.2
  TOP w0.2: R205.1@75.55,42.2 75.55,42.4 76,41.95 76,41.6
  other v2: 72.85,42.5 73.65,42.5 72.85,43.3 73.65,43.3
DH1: D203.C IC202.40 pad.@67.3,39.95 R202.2 | length 10.1
  BOTTOM w0.5: R202.2@66.74,46.2 66.74,45.589 67.139,45.19 ; pad.@67.3,39.95 68.25,40.9 68.25,43.2 67.278,44.172 67.278,44.931 67.229,44.882 67.229,45.1 67.139,45.19 ; D203.C@67.6,47.7 67.6,45.65 67.139,45.19
DH1_Q: Q203.3 R202.1 R203.1 R208.2 TP204.1
DH2: D205.C IC202.37 pad.@69.45,40.6 R215.2
DH2_Q: Q205.3 R211.2 R213.1 R215.1 TP209.1
DL1: D204.C IC202.2 pad.@66,38.55 R201.2
DL1_Q: Q204.3 R201.1 R207.1 R209.2 TP206.1
DL2: D206.C IC202.35 pad.@71.2,41 R216.2
DL2_Q: Q206.3 R212.2 R214.1 R216.1 TP211.1
GDRV: IC202.8 Q207.4 R220.2 TP214.1 | length 36.8
  Mid-Layer 2 w0.3: v1(65.5,34) 66.35,33.15 66.35,31.65 66,31.3 66,29.2 68.25,26.95 89.65,26.95 91.75,24.85 91.75,22.776 TP214.1@90.437,21.463
GND_A: C239.1 C240.1 C241.1 C242.2 C243.2 C245.2 C246.2 C249.1 C250.1 C251.1 C252.1 C253.1 C254.1 CN202.1T CN202.2T CN202.5 IC202.23 IC202.26 pad.@57.45,27.15 pad.@58.45,27.15 R229.2 R235.2 R237.2 R241.1 TP218.1 | length 8.7
  TOP w0.2: IC202.23@72.898,34.5 73.55,34.5 74.6,33.45
  BOTTOM w0.3: 76.75,31.6 C252.1@76.75,32.325 ; C253.1@79.27,37.981 82.046,37.981 ; R241.1@81.017,34.24 82.292,34.24 ; C254.1@81.024,36.972 81.899,36.972 ; R237.2@81.11,39.039 81.981,39.039
  other v1: 72.9,28.7 68.875,28.725 75.75,31.55 108.5,37.5 108.5,39 108.5,40.5 108.5,42 108.5,43.5
GND_P: C202.1 C203.1 C204.1 C206.1 C207.1 C208.1 C209.1 C211.1 C212.1 C213.1 C214.1 C216.1 C218.1 C219.2 C222.1 C223.1 C224.1 C225.1 C226.1 C227.1 C228.1 C229.1 C230.1 C231.1 C232.1 C233.1 C234.1 C235.1 C236.1 C237.1 C238.1 CN201.1T CN201.2 CN201.2T CN201.3T CN201.4T D201.A IC201.2 IC201.5 IC202.3 IC202.41 Q204.4 Q206.4 Q207.1 Q207.2 Q207.3 R209.1 R212.1 R219.1 R220.1 R229.1 TP207.1 TP212.1 TP216.1 TP231.1 TP232.1 TP233.1 TP234.1 | length 95.4
  TOP w0.2: IC202.3@67.002,37 IC202.41@68.3,37
  TOP w0.3: 87.9,21.503 R220.1@88.626,21.503 88.626,22.25
  TOP w1: 22.93,31.76 CN201.1T@22.93,30.535 CN201.2T@25.23,30.535 ; 22.93,48.34 CN201.4T@22.93,49.565 CN201.3T@25.23,49.565 ; 25.23,29.31 CN201.2T@25.23,30.535 ; 25.23,31.76 CN201.2T@25.23,30.535 ; 25.23,48.34 CN201.3T@25.23,49.565 ; 25.23,50.79 CN201.3T@25.23,49.565 ; 26.455,30.535 CN201.2T@25.23,30.535 ; 26.455,49.565 CN201.3T@25.23,49.565
  TOP w2.032: 33.75,43.3 CN201.2@36.3,43.3 ; 36.3,45.85 CN201.2@36.3,43.3 ; 38.85,43.3 CN201.2@36.3,43.3
  Mid-Layer 1 w1: 22.93,32.01 CN201.1T@22.93,30.535 CN201.2T@25.23,30.535 ; 22.93,48.057 CN201.4T@22.93,49.565 CN201.3T@25.23,49.565 ; 25.23,29.06 CN201.2T@25.23,30.535 ; 25.23,32.01 CN201.2T@25.23,30.535 ; 25.23,48.09 CN201.3T@25.23,49.565 ; 25.23,51.04 CN201.3T@25.23,49.565 ; 26.705,30.535 CN201.2T@25.23,30.535 ; 26.705,49.565 CN201.3T@25.23,49.565
  Mid-Layer 1 w2.032: 34,43.3 CN201.2@36.3,43.3 ; CN201.2@36.3,41.6 CN201.2@36.3,43.3 ; 36.3,45.6 CN201.2@36.3,43.3 ; 38.6,43.3 CN201.2@36.3,43.3
  Mid-Layer 2 w1: 22.93,32.01 CN201.1T@22.93,30.535 CN201.2T@25.23,30.535 ; 22.93,47.973 CN201.4T@22.93,49.565 CN201.3T@25.23,49.565 ; 25.23,29.06 CN201.2T@25.23,30.535 ; 25.23,32.01 CN201.2T@25.23,30.535 ; 25.23,47.973 CN201.3T@25.23,49.565 ; 25.23,51.04 CN201.3T@25.23,49.565 ; 26.705,30.535 CN201.2T@25.23,30.535 ; 26.705,49.565 CN201.3T@25.23,49.565
  Mid-Layer 2 w2.032: 34,43.3 CN201.2@36.3,43.3 ; CN201.2@36.3,41.65 CN201.2@36.3,43.3 ; 36.3,45.6 CN201.2@36.3,43.3 ; 38.6,43.3 CN201.2@36.3,43.3
  BOTTOM w0.3: 51.475,35.8 IC201.2@51.475,37.425
  BOTTOM w1: 22.93,31.76 CN201.1T@22.93,30.535 CN201.2T@25.23,30.535 ; 22.93,48.34 CN201.4T@22.93,49.565 CN201.3T@25.23,49.565 ; 25.23,29.31 CN201.2T@25.23,30.535 ; 25.23,31.76 CN201.2T@25.23,30.535 ; 25.23,48.34 CN201.3T@25.23,49.565 ; 25.23,50.79 CN201.3T@25.23,49.565 ; 26.455,30.535 CN201.2T@25.23,30.535 ; 26.455,49.565 CN201.3T@25.23,49.565
  BOTTOM w2.032: 34.15,43.3 CN201.2@36.3,43.3 36.3,45.45
  other v1: 27.6,21.35 29.6,21.35 31.6,21.35 33.05,21.35 34.8,21.35 38.8,21.35 40,21.35 61.75,21.5 64.25,21.5 66.75,21.5 69.25,21.5 71.75,21.5 74.25,21.5 76.75,21.5 77.8,21.8 78.7,21.8 79.6,21.8 80.5,21.8 81.4,21.8 82.3,21.8 83.2,21.8 84.1,21.8 85,21.8 85.9,21.8 86.8,21.8 87.7,21.8 77.8,22.7 78.7,22.7 79.6,22.7 80.5,22.7 81.4,22.7 82.3,22.7 83.2,22.7 84.1,22.7 85,22.7 85.9,22.7 86.8,22.7 87.7,22.7 77.8,23.6 78.7,23.6 79.6,23.6 80.5,23.6 81.4,23.6 82.3,23.6 83.2,23.6 84.1,23.6 85,23.6 85.9,23.6 86.8,23.6 87.7,23.6 27.6,23.85 29.6,23.85 77.8,24.5 78.7,24.5 79.6,24.5 80.5,24.5 81.4,24.5 82.3,24.5 83.2,24.5 84.1,24.5 85,24.5 85.9,24.5 86.8,24.5 87.7,24.5 77.8,25.4 78.7,25.4 79.6,25.4 80.5,25.4 81.4,25.4 82.3,25.4 83.2,25.4 84.1,25.4 85,25.4 85.9,25.4 86.8,25.4 87.7,25.4 26.4,27.95 28.9,27.95 80.5,29 81.4,29 82.3,29 83.2,29 84.1,29 85,29 88.5,29 89.4,29 90.3,29 91.2,29 92.1,29 93,29 55.25,32.25 56.15,32.25 57.05,32.25 57.95,32.25 21.4,32.95 23.9,32.95 26.4,32.95 28.9,32.95 54.35,33.15 55.25,33.15 56.15,33.15 57.05,33.15 57.95,33.15 54.35,34.05 55.25,34.05 56.15,34.05 57.05,34.05 57.95,34.05 54.35,34.95 55.25,34.95 56.15,34.95 57.05,34.95 57.95,34.95 21.4,35.45 23.9,35.45 26.4,35.45 28.9,35.45 54.35,35.85 55.25,35.85 56.15,35.85 57.05,35.85 57.95,35.85 54.35,36.75 55.25,36.75 56.15,36.75 57.05,36.75 57.95,36.75 65.25,37.25 64.5,37.7 21.4,37.95 23.9,37.95 26.4,37.95 28.9,37.95 21.4,40.45 23.9,40.45 26.4,40.45 28.9,40.45 31.4,40.45 21.4,42.95 23.9,42.95 26.4,42.95 28.9,42.95 31.4,42.95 21.4,45.45 23.9,45.45 26.4,45.45 28.9,45.45 31.4,45.45 33.9,45.45 81.25,46 82.15,46 83.05,46 83.95,46 84.85,46 85.75,46 86.65,46 87.55,46 38.9,46.3 81.25,46.9 82.15,46.9 83.05,46.9 83.95,46.9 84.85,46.9 85.75,46.9 86.65,46.9 87.55,46.9 39.9,47.1 81.25,47.8 82.15,47.8 83.05,47.8 83.95,47.8 84.85,47.8 85.75,47.8 86.65,47.8 87.55,47.8 21.4,47.95 23.9,47.95 26.4,47.95 28.9,47.95 31.4,47.95 33.9,47.95 38.9,47.95 40.7,47.95 81.25,48.7 82.15,48.7 83.05,48.7 83.95,48.7 84.85,48.7 85.75,48.7 86.65,48.7 87.55,48.7 41.55,48.75 38.9,49.55 40.7,49.55 42.3,49.55 81.25,49.6 82.15,49.6 83.05,49.6 83.95,49.6 84.85,49.6 85.75,49.6 86.65,49.6 87.55,49.6 43.2,50.35 31.4,51.1 33.9,51.1 36.4,51.1 38.9,51.1 41.4,51.1 43.9,51.1 31.4,53.6 33.9,53.6 36.4,53.6 38.9,53.6 41.4,53.6 81.25,55.8 82.15,55.8 83.05,55.8 83.95,55.8 84.85,55.8 85.75,55.8 86.65,55.8 87.55,55.8 88.45,55.8 91.5,55.8 92.4,55.8 93.3,55.8 94.2,55.8 95.1,55.8 96,55.8 96.9,55.8 97.8,55.8 98.7,55.8 43.9,56.1 81.25,56.7 82.15,56.7 83.05,56.7 83.95,56.7 84.85,56.7 85.75,56.7 86.65,56.7 87.55,56.7 88.45,56.7 91.5,56.7 92.4,56.7 93.3,56.7 94.2,56.7 95.1,56.7 96,56.7 96.9,56.7 97.8,56.7 98.7,56.7 81.25,57.6 82.15,57.6 83.05,57.6 83.95,57.6 84.85,57.6 85.75,57.6 86.65,57.6 87.55,57.6 88.45,57.6 91.5,57.6 92.4,57.6 93.3,57.6 94.2,57.6 95.1,57.6 96,57.6 96.9,57.6 97.8,57.6 98.7,57.6 53.75,58.5 81.25,58.5 82.15,58.5 83.05,58.5 83.95,58.5 84.85,58.5 85.75,58.5 86.65,58.5 87.55,58.5 88.45,58.5 91.5,58.5 92.4,58.5 93.3,58.5 94.2,58.5 95.1,58.5 96,58.5 96.9,58.5 97.8,58.5 98.7,58.5 31.4,58.6 33.9,58.6 36.4,58.6 38.9,58.6 41.4,58.6 43.9,58.6 46.4,58.6 48.9,58.6 51.4,58.6
  other v2: 68.3,34.1 71.6,34.1 68.3,37.4 71.6,37.4 63,38.45 63.85,38.45 63,39.35 63.85,39.35 63,40.25 63.85,40.25
HVCC1: C250.2 CN203.7 IC202.25 | length 37.1
  TOP w0.3: CN203.7@100.735,43 100.835,42.9 v1(103.45,42.9)
  Mid-Layer 2 w0.3: v1(74.8,35.1) 95.65,35.1 v1(103.45,42.9)
  BOTTOM w0.3: v1@103.45,42.864 C250.2@104.667,42.864 104.631,42.9 v1(103.45,42.9)
HVCC2: C249.2 CN203.6 IC202.24 | length 35.3
  TOP w0.3: CN203.6@100.735,41 v1(103.45,41)
  Mid-Layer 2 w0.3: v1(74.8,34.2) 75.939,34.2 76.289,34.55 95.856,34.55 102.306,41 v1(103.45,41)
  BOTTOM w0.3: v1(103.45,41) 104.572,41 C249.2@104.594,41.022
HVDM: CN203.5 IC202.21 | length 35.1
  TOP w0.3: CN203.5@100.735,39 v1(103.45,39)
  Mid-Layer 2 w0.3: v1(73.65,32.85) 74.45,32.85 74.52,32.92 97.37,32.92 v1(103.45,39)
HVDP: CN203.4 IC202.22 | length 33.5
  TOP w0.3: CN203.4@100.735,37 v1(103.45,37)
  Mid-Layer 2 w0.3: v1(74.7,32.1) 74.925,32.325 97.482,32.325 102.157,37 v1(103.45,37)
HVEN: IC202.6 pad.@65.5,35.35 R234.2 R235.1 | length 9.1
  BOTTOM w0.2: R234.2@70.425,31 70.425,30.1 70.45,30.075 R235.1@70.5,30.025
  BOTTOM w0.3: pad.@65.5,35.35 67.6,33.25 68.6,33.25 70.45,31.4 70.45,30.075 70.45,29.975 R235.1@70.5,30.025
LX1: C217.2 IC202.39 L202.1 Q203.4 Q204.1 Q204.2 Q204.5 Q204.6 R208.1 TP205.1 | length 8
  Mid-Layer 1 w0.5: TP205.1@62.85,47.65 65.1,47.65 67.3,45.45 v1(67.3,42.85)
  other v2: 65.3,43.45 66.15,43.45 65.3,44.3 66.15,44.3
LX2: C220.2 IC202.38 L202.2 Q205.4 Q206.1 Q206.2 Q206.5 Q206.6 R211.1 TP210.1 | length 5.9
  Mid-Layer 1 w0.5: v1(69.15,42.8) 69.15,45.45 70.3,46.6 TP210.1@71.9,46.6
  other v2: 76.9,48.15 77.7,48.15 76.9,49.15 77.7,49.15
OUT: C223.2 C224.2 C225.2 C226.2 C227.2 C228.2 C229.2 C230.2 C231.2 C232.2 C233.2 pad.@76.75,41.15 pad.@91.7,43.2 R205.2 R206.1 R231.1 | length 18.4
  TOP w0.2: pad.@91.7,43.2 92.15,43.2 92.294,43.344 92.663,43.344 93.206,42.8 R206.1@94,42.8
  BOTTOM w0.3: pad.@76.75,41.15 76.9,41.3 89.8,41.3 pad.@91.7,43.2
SCL: CN202.3 pad.@52.8,26.55 R222.2 R227.2 | length 9.6
  TOP w0.5: pad.@52.8,26.55 53.121,26.871 CN202.3@53.121,29.217
  BOTTOM w0.3: R222.2@52.8,27.575 pad.@52.8,26.55 54.85,24.5 R227.2@57.725,24.5
SDA: CN202.4 pad.@54.6,26.55 R221.2 R228.2 | length 7.5
  TOP w0.5: pad.@54.6,26.55 55.121,27.071 CN202.4@55.121,29.217
  BOTTOM w0.3: R221.2@54.6,27.575 pad.@54.6,26.55 55.45,25.7 R228.2@57.825,25.7
SHLD_SNS: C238.2 CN203.1 CN203.1T CN203.2 CN203.2T CN203.3 IC202.7 Q207.5 TP215.1 | length 38.3
  TOP w0.2: v1(64.45,34) 65.15,34.7 66.2,34.7 66.5,35 IC202.7@67.002,35
  Mid-Layer 2 w0.3: v1(64.45,34) 64.45,34.45 64.7,34.7 66.15,34.7 67.8,33.05 67.8,28.5 68.7,27.6 89.85,27.6 92.55,24.9
  other v1: 93,21.4 94.5,21.4 96,21.5 97.25,21.5 98.5,21.5 92.55,22.25 93.4,22.25 94.25,22.25 95.1,22.25 99.5,22.25 100.5,23.25 101.5,24.25 92.55,25.65 93.4,25.65 94.25,25.65 95.1,25.65 95.25,27.25 96.25,27.25 97.25,27.25 98.25,28 99,28.75 103.45,30.55 104.35,30.55 105.25,30.55 106.15,30.55 103.45,31.45 104.35,31.45 105.25,31.45 106.15,31.45 103.45,32.35 104.35,32.35 105.25,32.35 106.15,32.35 103.45,33.25 104.35,33.25 105.25,33.25 106.15,33.25
SIG247: C218.2 D201.C IC201.6 R210.1
SIG310: C251.2 IC202.27 pad.@73.9,36.6 R233.2 | length 4.1
  BOTTOM w0.3: pad.@73.9,36.6 75.062,36.6 75.722,35.941 75.722,35.029 75.734,35.041 R233.2@76.784,35.041
SIG311: C252.2 R233.1 | length 0.8
  BOTTOM w0.3: C252.2@76.75,33.175 R233.1@76.75,34.025
SIG313: C254.2 R236.1 R238.2 | length 1.9
  BOTTOM w0.3: R238.2@79.113,36.027 79.254,36.168 R236.1@79.254,36.97 80.173,36.97 C254.2@80.174,36.972
SIG316: C255.1 R240.1 R241.2 | length 1.9
  BOTTOM w0.3: R240.1@79.275,34.251 80.156,34.251 R241.2@80.167,34.24 80.167,35.042 C255.1@80.306,35.181
SIG317: C255.2 R238.1
SIG318: C253.2 IC202.30 pad.@73.85,38.55 R236.2 R240.2 | length 8.7
  BOTTOM w0.3: pad.@73.85,38.55 74.2,38.2 76.6,38.2 76.819,37.981 C253.2@78.42,37.981 R236.2@78.42,36.853 ; R236.2@78.404,36.97 78.404,34.273 R240.2@78.425,34.251
SIG319: C247.1 C248.2 IC202.32 R231.2 | length 1.9
  TOP w0.2: IC202.32@71.7,38.948 71.7,39 72.875,40.175 C247.1@73.1,40.175
SIG324: C248.1 IC202.31 R232.2 | length 2.5
  TOP w0.2: IC202.31@72.2,38.948 72.398,38.948 72.725,39.275 C248.1@74.575,39.275
SIG328: C247.2 IC202.33 R230.2 | length 3.1
  TOP w0.2: IC202.33@71.2,38.8 71.2,39.1 73.113,41.013 C247.2@73.175,40.95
